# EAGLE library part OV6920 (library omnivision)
CMOS Analaog NTSC CAMERACHIP (TM) Sensor with OmniPixel(R) Technology Source: http://www.ovt.com .. OV6920_DS+(1.1).pdf
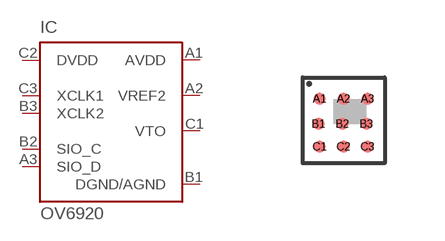
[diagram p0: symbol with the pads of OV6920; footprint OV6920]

Designator prefix IC

## OV6920 (OC_FARNELL: unknown; OC_NEWARK: unknown)  [OV6920]
A1  AVDD  in
A2  VREF2  in
A3  SIO_D
B1  DGND/AGND  in
B2  SIO_C  in
B3  XCLK2  out
C1  VTO  out
C2  DVDD  in
C3  XCLK1  in

## Footprint OV6920 (pad centres in mm)
CMOS Analaog NTSC CAMERACHIP (TM) Sensor with OmniPixel(R) Technology Source: http://www.ovt.com .. OV6920_DS+(1.1).pdf
smd 0.3 x 0.3: A1 -0.6,0.54; A2 0,0.54; A3 0.6,0.54; B1 -0.63,-0.09; B2 -0.03,-0.09; B3 0.57,-0.09; C1 -0.6,-0.66; C2 0,-0.66; C3 0.6,-0.66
